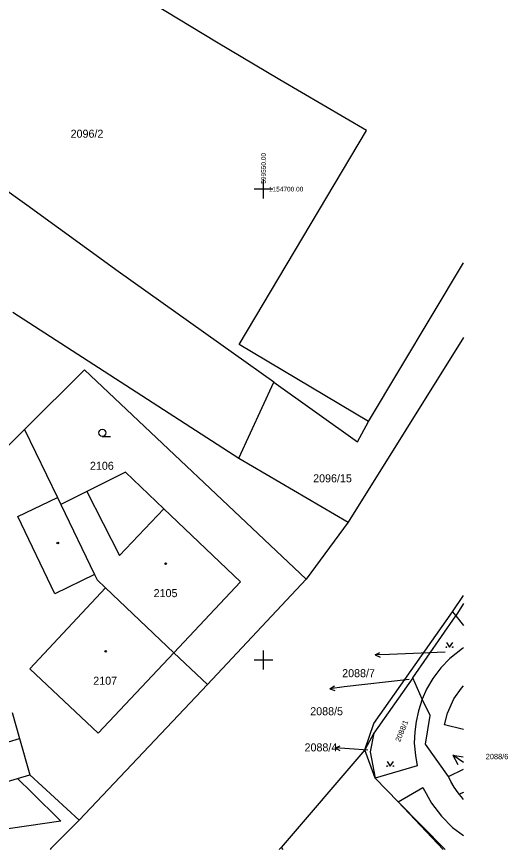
# Model space of a CAD drawing. Extents: x -599970 to -599524, y -1154772 to -1154457.
# Drawn here: x -599576.2 to -599524.1, y -1154770.1 to -1154681.7 of the extents above; entities that cross this region are included whole.
import ezdxf

# ---------------------------------------------------------------- set-up
doc = ezdxf.new("R2010")
doc.units = 0
for name, color, linetype in [('Z-KATASTRALNI MAPA', 7, 'Continuous'), ('Z-KRIZKY CTVERCOVE SITE', 7, 'Continuous'), ('Z-POPIS KRIZKU CTVERCOVE SITE', 7, 'Continuous')]:
    doc.layers.add(name, color=color, linetype=linetype)

msp = doc.modelspace()

# ---------------------------------------------------------------- linework, layer by layer
at = {"layer": 'Z-KATASTRALNI MAPA'}
for p, q in [((-599575.13, -1154701.69), (-599595.71, -1154687.03)), ((-599576.61, -1154713.05), (-599552.63, -1154728.55)), ((-599548.89, -1154720.51), (-599553.17, -1154717.45)), ((-599552.63, -1154728.55), (-599548.89, -1154720.51)), ((-599548.89, -1154720.51), (-599540.04, -1154726.82)), ((-599540.04, -1154726.82), (-599538.86, -1154724.66)), ((-599575.36, -1154725.51), (-599582.69, -1154732.79)), ((-599567.106, -1154726.25), (-599566.231, -1154726.25)), ((-599552.63, -1154728.55), (-599541.01, -1154735.37)), ((-599576.07, -1154734.77), (-599571.87, -1154732.74)), ((-599568.74, -1154732.11), (-599565.28, -1154738.9)), ((-599565.28, -1154738.9), (-599560.56, -1154733.96)), ((-599572.13, -1154742.96), (-599576.07, -1154734.77)), ((-599541.01, -1154735.37), (-599545.49, -1154741.41)), ((-599567.92, -1154740.93), (-599572.13, -1154742.96)), ((-599545.49, -1154741.41), (-599555.96, -1154752.59)), ((-599574.79, -1154750.92), (-599566.75, -1154742.33)), ((-599528.77, -1154744), (-599529.61, -1154745.29)), ((-599529.95, -1154744.87), (-599529.61, -1154745.29)), ((-599534.15, -1154751.88), (-599529.61, -1154745.29)), ((-599559.51, -1154749.22), (-599567.54, -1154757.76)), ((-599559.51, -1154749.22), (-599555.96, -1154752.59)), ((-599538.15, -1154749.453), (-599537.658, -1154749.184)), ((-599536.65, -1154749.4), (-599538.15, -1154749.453)), ((-599538.15, -1154749.453), (-599537.64, -1154749.685)), ((-599530.71, -1154749.17), (-599536.65, -1154749.4)), ((-599567.54, -1154757.76), (-599574.79, -1154750.92)), ((-599534.54, -1154752.07), (-599541.46, -1154752.86)), ((-599534.15, -1154751.88), (-599538.3, -1154757.76)), ((-599533.17, -1154754.16), (-599534.15, -1154751.88)), ((-599555.96, -1154752.59), (-599569.56, -1154767.01)), ((-599542.949, -1154753.043), (-599542.483, -1154752.734)), ((-599541.46, -1154752.86), (-599542.949, -1154753.043)), ((-599542.949, -1154753.043), (-599542.422, -1154753.231)), ((-599582.84, -1154760.47), (-599575.88, -1154758.32)), ((-599538.3, -1154757.76), (-599539.25, -1154759.52)), ((-599542.387, -1154759.326), (-599541.87, -1154759.11)), ((-599539.25, -1154759.52), (-599548.14, -1154769.9)), ((-599540.89, -1154759.43), (-599542.387, -1154759.326)), ((-599542.387, -1154759.326), (-599541.905, -1154759.61)), ((-599538.93, -1154759.57), (-599540.89, -1154759.43)), ((-599538.15, -1154762.54), (-599539.25, -1154759.52)), ((-599528.77, -1154760.89), (-599529.92, -1154760.11)), ((-599529.92, -1154760.11), (-599528.81, -1154760.26)), ((-599529.92, -1154760.11), (-599529.37, -1154761.09)), ((-599576.09, -1154762.58), (-599574.78, -1154762.19)), ((-599574.78, -1154762.19), (-599569.56, -1154767.01)), ((-599535.71, -1154765.07), (-599538.15, -1154762.54)), ((-599530.72, -1154770.1), (-599535.71, -1154765.07)), ((-599530.95, -1154770.1), (-599535.71, -1154765.07)), ((-599548.35, -1154770.1), (-599548.14, -1154769.9)), ((-599548.14, -1154769.9), (-599547.94, -1154770.1))]:
    msp.add_line(p, q, dxfattribs=at)
for points in [[(-599538.86, -1154724.66), (-599552.58, -1154716.5), (-599539.08, -1154693.79), (-599548.26, -1154688.39), (-599554.98, -1154684.38), (-599561.71, -1154680.31), (-599559.25, -1154676.23), (-599564.02, -1154674.97), (-599564.71, -1154677.61), (-599576.23, -1154674.72), (-599580.3, -1154673.63), (-599591.68, -1154670.69), (-599587.1, -1154652.88), (-599594.35, -1154651.03), (-599594.06, -1154649.91), (-599594.54, -1154649.78), (-599590.94, -1154635.97), (-599579.29, -1154639.04), (-599578.73, -1154636.91), (-599567.95, -1154639.74), (-599568.51, -1154641.87), (-599562.42, -1154643.47), (-599561.82, -1154641.2), (-599554.41, -1154642.98)], [(-599553.17, -1154717.45), (-599565.43, -1154708.75), (-599575.13, -1154701.69)], [(-599538.86, -1154724.66), (-599528.77, -1154707.81)], [(-599528.77, -1154715.74), (-599541.01, -1154735.37)], [(-599545.49, -1154741.41), (-599568.99, -1154719.19), (-599575.36, -1154725.51)], [(-599575.36, -1154725.51), (-599571.87, -1154732.74), (-599571.51, -1154733.5)], [(-599559.51, -1154749.22), (-599552.45, -1154741.71), (-599560.56, -1154733.96), (-599564.65, -1154730.05), (-599568.74, -1154732.11), (-599571.51, -1154733.5)], [(-599571.51, -1154733.5), (-599567.92, -1154740.93), (-599567.66, -1154741.47)], [(-599567.66, -1154741.47), (-599566.75, -1154742.33), (-599559.51, -1154749.22)], [(-599529.95, -1154744.87), (-599528.77, -1154743.16)], [(-599539.25, -1154759.52), (-599538.3, -1154756.73), (-599529.95, -1154744.87)], [(-599529.61, -1154745.29), (-599528.77, -1154746.32)], [(-599530.595, -1154748.127), (-599530.26, -1154748.63), (-599529.925, -1154748.127)], [(-599528.77, -1154748.71), (-599528.9, -1154748.79), (-599530.22, -1154749.82), (-599531.2, -1154750.83), (-599532.04, -1154751.95), (-599532.72, -1154753.1), (-599533.17, -1154754.16)], [(-599528.77, -1154757.36), (-599530.81, -1154756.87), (-599530.48, -1154755.65), (-599529.82, -1154754.13), (-599529.01, -1154753), (-599528.77, -1154752.75)], [(-599533.17, -1154754.16), (-599533.57, -1154755.39), (-599533.81, -1154756.51), (-599533.95, -1154757.61), (-599534, -1154758.84), (-599533.89, -1154760.12), (-599533.7, -1154761.25), (-599538.15, -1154762.54)], [(-599530.38, -1154762.36), (-599532.82, -1154758.93), (-599532.33, -1154755.88), (-599533.03, -1154754.42), (-599533.17, -1154754.16)], [(-599576.67, -1154755.56), (-599575.88, -1154758.32), (-599574.78, -1154762.19)], [(-599538.3, -1154757.76), (-599538.69, -1154759.76), (-599538.15, -1154762.54)], [(-599536.885, -1154760.757), (-599536.55, -1154761.26), (-599536.215, -1154760.757)], [(-599530.38, -1154762.36), (-599528.77, -1154761.57)], [(-599576.09, -1154762.58), (-599574.57, -1154764.07), (-599571.5, -1154767.11), (-599587.3, -1154769.4), (-599588.27, -1154766.17)], [(-599588.27, -1154766.17), (-599582.73, -1154764.55), (-599581.69, -1154764.24), (-599576.09, -1154762.58)], [(-599529.24, -1154764.24), (-599529.36, -1154764.09), (-599529.77, -1154763.5), (-599530.12, -1154762.88), (-599530.38, -1154762.36)], [(-599535.71, -1154765.07), (-599533.08, -1154763.55), (-599532.17, -1154765.2), (-599531.11, -1154766.57), (-599529.94, -1154767.77), (-599528.77, -1154768.63)], [(-599528.77, -1154764.05), (-599529.24, -1154764.24)], [(-599528.77, -1154764.79), (-599529.01, -1154764.54), (-599529.24, -1154764.24)], [(-599569.56, -1154767.01), (-599572.55, -1154770.02), (-599572.65, -1154770.1)]]:
    msp.add_lwpolyline(points, dxfattribs=at)
for centre, radius in [((-599567.106, -1154725.875), 0.375), ((-599571.833, -1154737.58), 0.0875), ((-599560.383, -1154739.77), 0.0875), ((-599530.595, -1154748.63), 0.0335), ((-599529.925, -1154748.63), 0.0335), ((-599566.743, -1154749.07), 0.0875), ((-599536.885, -1154761.26), 0.0335), ((-599536.215, -1154761.26), 0.0335)]:
    msp.add_circle(centre, radius, dxfattribs=at)
at = {"layer": 'Z-KRIZKY CTVERCOVE SITE'}
for p, q in [((-599550, -1154701), (-599550, -1154699)), ((-599549, -1154700), (-599551, -1154700)), ((-599550, -1154751), (-599550, -1154749)), ((-599549, -1154750), (-599551, -1154750))]:
    msp.add_line(p, q, dxfattribs=at)

# ---------------------------------------------------------------- texts
at = {"layer": 'Z-KATASTRALNI MAPA'}
for s, height, p in [('2096/2', 0.85, (-599570.468, -1154694.54)), ('2106', 0.85, (-599568.418, -1154729.8)), ('2096/15', 0.85, (-599544.735, -1154731.13)), ('2105', 0.85, (-599561.661, -1154743.32)), ('2088/7', 0.85, (-599541.656, -1154751.82)), ('2107', 0.85, (-599568.068, -1154752.62)), ('2088/5', 0.85, (-599545.043, -1154755.86)), ('2088/4', 0.85, (-599545.646, -1154759.7)), ('2088/6', 0.5695, (-599526.425, -1154760.53))]:
    msp.add_text(s, height=height, dxfattribs=at).set_placement(p)
msp.add_text('2088/1', height=0.57, rotation=68, dxfattribs=at).set_placement((-599535.523, -1154758.751))
at = {"layer": 'Z-POPIS KRIZKU CTVERCOVE SITE'}
msp.add_text('   599550.00', height=0.5, rotation=90, dxfattribs=at).set_placement((-599549.75, -1154700))
msp.add_text('   1154700.00', height=0.5, dxfattribs=at).set_placement((-599550, -1154700.25))

doc.saveas('drawing.dxf')
